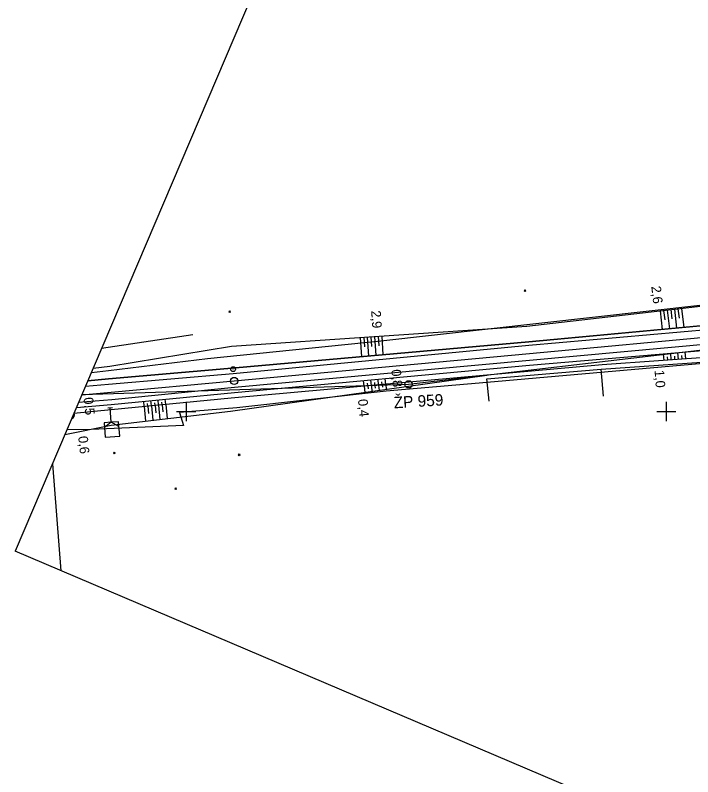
# Model space of a CAD drawing. Extents: x -805636 to -804553, y -1165340 to -1164656.
# Drawn here: x -805635.6 to -805494.5, y -1164976.1 to -1164817.4 of the extents above; entities that cross this region are included whole.
import ezdxf

# ---------------------------------------------------------------- set-up
doc = ezdxf.new("R2010")
doc.units = 0
for name, color, linetype in [('0381KM061-064P - Vrstva 1', 7, 'Continuous'), ('0381KM061-064P - Vrstva 17', 7, 'Continuous'), ('0381KM061-064P - Vrstva 4', 7, 'Continuous'), ('0381KM061-064P - Vrstva 48', 7, 'Continuous'), ('0381KM061-064P - Vrstva 49', 7, 'Continuous'), ('0381KM061-064P - Vrstva 7', 7, 'Continuous'), ('0381KM061-064P - Vrstva 8', 7, 'Continuous'), ('formát', 7, 'Continuous'), ('hran DP - hran DP', 7, 'Continuous'), ('krizky_1000 - Vrstva 1', 7, 'Continuous'), ('vyt_sit - polygon', 7, 'Continuous'), ('vyt_sit - stávající', 7, 'Continuous')]:
    doc.layers.add(name, color=color, linetype=linetype)

msp = doc.modelspace()

# ---------------------------------------------------------------- linework, layer by layer
at = {"layer": '0381KM061-064P - Vrstva 1'}
msp.add_lwpolyline([(-805621.7, -1164896.48), (-805615.58, -1164895.98), (-805590.01, -1164893.62), (-805528.48, -1164887.9), (-805486.76, -1164883.98), (-805461.3, -1164882.03), (-805437.69, -1164881.51), (-805413.27, -1164883.66)], dxfattribs=at)
at = {"layer": '0381KM061-064P - Vrstva 17'}
for p, q in [((-805598.57, -1164884.01), (-805617.61, -1164886.87)), ((-805513.07, -1164896.77), (-805513.54, -1164891.19))]:
    msp.add_line(p, q, dxfattribs=at)
msp.add_lwpolyline([(-805536.86, -1164897.86), (-805537.37, -1164893.17), (-805513.54, -1164891.19), (-805489.69, -1164889.49), (-805460.65, -1164887.61), (-805460.29, -1164888.19), (-805437.32, -1164886.99), (-805436.25, -1164891.59)], dxfattribs=at)
at = {"layer": '0381KM061-064P - Vrstva 4'}
for p, q in [((-805528.63, -1164885.47), (-805490.63, -1164881.9)), ((-805490.28, -1164882.82), (-805528.62, -1164886.23)), ((-805589.69, -1164890.91), (-805528.63, -1164885.47)), ((-805528.62, -1164886.23), (-805590.21, -1164892.16)), ((-805616.18, -1164893.18), (-805589.69, -1164890.91)), ((-805620.48, -1164893.61), (-805616.18, -1164893.18)), ((-805590.21, -1164892.16), (-805616.16, -1164894.34)), ((-805616.16, -1164894.34), (-805620.98, -1164894.78))]:
    msp.add_line(p, q, dxfattribs=at)
for points in [[(-805622.83, -1164899.13), (-805615.58, -1164898.49), (-805589.92, -1164896.02), (-805528.49, -1164890.34), (-805490.03, -1164887.06), (-805461.18, -1164884.75), (-805437.91, -1164883.87), (-805413.61, -1164886.43), (-805397.33, -1164889.69), (-805391.36, -1164890.97), (-805383.82, -1164892.41)], [(-805383.82, -1164892.41), (-805391.14, -1164890.05), (-805413.4, -1164885.24), (-805437.69, -1164883.08), (-805461.24, -1164883.62), (-805489.81, -1164885.79), (-805528.46, -1164889.37), (-805589.94, -1164895), (-805615.48, -1164897.55), (-805622.38, -1164898.08)]]:
    msp.add_lwpolyline(points, dxfattribs=at)
at = {"layer": '0381KM061-064P - Vrstva 48'}
for p, q in [((-805501.3, -1164879), (-805500.85, -1164882.86)), ((-805500.56, -1164878.91), (-805500.33, -1164880.85)), ((-805499.81, -1164878.83), (-805499.36, -1164882.72)), ((-805499.07, -1164878.74), (-805498.84, -1164880.7)), ((-805498.32, -1164878.66), (-805497.87, -1164882.58)), ((-805497.58, -1164878.57), (-805497.35, -1164880.54)), ((-805496.83, -1164878.48), (-805496.37, -1164882.44)), ((-805563.76, -1164884.57), (-805563.49, -1164888.58)), ((-805563.01, -1164884.52), (-805562.88, -1164886.51)), ((-805562.27, -1164884.47), (-805562, -1164888.44)), ((-805561.52, -1164884.42), (-805561.38, -1164886.4)), ((-805560.77, -1164884.36), (-805560.5, -1164888.31)), ((-805560.02, -1164884.31), (-805559.89, -1164886.28)), ((-805559.27, -1164884.26), (-805559.01, -1164888.18)), ((-805500.46, -1164889.32), (-805500.56, -1164887.96)), ((-805499.71, -1164889.27), (-805499.76, -1164888.58)), ((-805498.96, -1164889.21), (-805499.06, -1164887.83)), ((-805498.21, -1164889.16), (-805498.26, -1164888.46)), ((-805497.46, -1164889.11), (-805497.57, -1164887.7)), ((-805496.72, -1164889.05), (-805496.77, -1164888.34)), ((-805495.97, -1164889), (-805496.07, -1164887.57)), ((-805562.92, -1164894.73), (-805563.03, -1164893.53)), ((-805561.43, -1164894.6), (-805561.53, -1164893.4)), ((-805559.93, -1164894.46), (-805560.04, -1164893.26)), ((-805558.44, -1164894.33), (-805558.55, -1164893.12)), ((-805562.92, -1164894.73), (-805562.81, -1164895.99)), ((-805562.17, -1164894.66), (-805562.23, -1164894.06)), ((-805562.17, -1164894.66), (-805562.12, -1164895.27)), ((-805561.43, -1164894.6), (-805561.32, -1164895.78)), ((-805560.68, -1164894.53), (-805560.73, -1164893.93)), ((-805560.68, -1164894.53), (-805560.63, -1164895.1)), ((-805559.93, -1164894.46), (-805559.83, -1164895.57)), ((-805559.19, -1164894.4), (-805559.24, -1164893.79)), ((-805559.19, -1164894.4), (-805559.14, -1164894.93)), ((-805558.44, -1164894.33), (-805558.35, -1164895.36)), ((-805608.72, -1164898.95), (-805608.83, -1164897.84)), ((-805607.97, -1164898.88), (-805608.03, -1164898.32)), ((-805607.23, -1164898.81), (-805607.33, -1164897.7)), ((-805606.48, -1164898.74), (-805606.53, -1164898.18)), ((-805605.73, -1164898.67), (-805605.84, -1164897.55)), ((-805604.99, -1164898.59), (-805605.04, -1164898.04)), ((-805604.24, -1164898.52), (-805604.35, -1164897.41)), ((-805608.72, -1164898.95), (-805608.43, -1164902)), ((-805607.97, -1164898.88), (-805607.83, -1164900.4)), ((-805607.23, -1164898.81), (-805606.94, -1164901.82)), ((-805606.48, -1164898.74), (-805606.34, -1164900.24)), ((-805605.73, -1164898.67), (-805605.45, -1164901.65)), ((-805604.99, -1164898.59), (-805604.84, -1164900.08)), ((-805604.24, -1164898.52), (-805603.96, -1164901.47))]:
    msp.add_line(p, q, dxfattribs=at)
at = {"layer": '0381KM061-064P - Vrstva 49'}
for p, q in [((-805529.26, -1164875), (-805529.61, -1164874.64)), ((-805529.26, -1164874.64), (-805529.61, -1164875)), ((-805590.78, -1164879.37), (-805591.13, -1164879.01)), ((-805590.78, -1164879.01), (-805591.13, -1164879.37)), ((-805614.8, -1164908.81), (-805615.15, -1164908.45)), ((-805614.8, -1164908.45), (-805615.15, -1164908.81)), ((-805588.77, -1164909.21), (-805589.13, -1164908.86)), ((-805588.77, -1164908.86), (-805589.13, -1164909.21)), ((-805602, -1164916.26), (-805602.35, -1164915.9)), ((-805602, -1164915.9), (-805602.35, -1164916.26))]:
    msp.add_line(p, q, dxfattribs=at)
for points in [[(-805619.35, -1164890.95), (-805615.91, -1164890.53), (-805590.56, -1164886.39), (-805529.03, -1164882.21), (-805489.9, -1164877.68), (-805461.98, -1164874.39), (-805438.96, -1164873.66), (-805412.14, -1164878.2), (-805389.29, -1164884.48), (-805375.6, -1164889.14)], [(-805379.56, -1164889.14), (-805389.79, -1164885.89), (-805412.78, -1164881.05), (-805437.82, -1164878.81), (-805461.56, -1164879.34), (-805490.63, -1164881.9), (-805528.63, -1164885.47), (-805589.69, -1164890.91), (-805616.18, -1164893.18), (-805620.48, -1164893.61)], [(-805622.83, -1164899.13), (-805615.58, -1164898.49), (-805589.92, -1164896.02), (-805528.49, -1164890.34), (-805490.03, -1164887.06), (-805461.18, -1164884.75), (-805437.91, -1164883.87), (-805413.61, -1164886.43), (-805397.33, -1164889.69), (-805394.79, -1164892.28)], [(-805394.79, -1164892.28), (-805397.93, -1164890.9), (-805413.8, -1164887.77), (-805437.96, -1164885.62), (-805460.38, -1164886.37), (-805489.93, -1164888.57), (-805513.35, -1164890.24), (-805537.4, -1164892.44), (-805590.64, -1164897.22), (-805615.62, -1164899.61), (-805623.38, -1164900.43)], [(-805625.24, -1164904.79), (-805615.6, -1164902.86), (-805590.78, -1164899.89), (-805537.4, -1164892.44)]]:
    msp.add_lwpolyline(points, dxfattribs=at)
at = {"layer": '0381KM061-064P - Vrstva 7'}
for p, q in [((-805590.27, -1164891.15), (-805590.17, -1164891.14)), ((-805615.33, -1164899.2), (-805616.33, -1164899.28)), ((-805615.58, -1164902.23), (-805615.83, -1164899.24))]:
    msp.add_line(p, q, dxfattribs=at)
for points in [[(-805615.58, -1164902.23), (-805617.08, -1164902.35), (-805616.83, -1164905.34), (-805613.84, -1164905.1), (-805614.09, -1164902.11), (-805615.58, -1164902.23)], [(-805614, -1164903.1), (-805615.58, -1164902.23), (-805616.99, -1164903.35)]]:
    msp.add_lwpolyline(points, dxfattribs=at)
for centre, radius in [((-805590.22, -1164891.15), 0.5), ((-805590, -1164893.62), 0.75)]:
    msp.add_circle(centre, radius, dxfattribs=at)
at = {"layer": '0381KM061-064P - Vrstva 8'}
for p, q in [((-805623.32, -1164900.29), (-805623.86, -1164901.55)), ((-805627.84, -1164910.91), (-805626.08, -1164933.16))]:
    msp.add_line(p, q, dxfattribs=at)
msp.add_arc((-805624.26, -1164900.63), 1, 293.9534, 19.9498, dxfattribs=at)
at = {"layer": 'formát'}
for p in [(-805519.31, -1164655.82), (-805055.88, -1165175.77)]:
    msp.add_line(p, (-805635.59, -1164929.12), dxfattribs=at)
at = {"layer": 'hran DP - hran DP'}
for p, q in [((-805559.43, -1164885.25), (-805493.02, -1164877.83)), ((-805595.52, -1164888.96), (-805559.43, -1164885.25)), ((-805472.98, -1164888.24), (-805537.37, -1164893.92)), ((-805616.15, -1164891.42), (-805595.52, -1164888.96)), ((-805619.74, -1164891.88), (-805616.15, -1164891.42)), ((-805537.37, -1164893.92), (-805558.32, -1164895.77)), ((-805558.32, -1164895.77), (-805589.42, -1164899.19)), ((-805589.42, -1164899.19), (-805601.38, -1164900.18)), ((-805601.38, -1164900.18), (-805600.58, -1164902.92)), ((-805600.58, -1164902.92), (-805621.39, -1164903.78)), ((-805621.39, -1164903.78), (-805624.8, -1164903.76))]:
    msp.add_line(p, q, dxfattribs=at)
at = {"layer": 'krizky_1000 - Vrstva 1'}
for points in [[(-805600, -1164898), (-805600, -1164902)], [(-805500, -1164898), (-805500, -1164902)], [(-805602, -1164900), (-805598, -1164900)], [(-805502, -1164900), (-805498, -1164900)]]:
    msp.add_lwpolyline(points, dxfattribs=at)
at = {"layer": 'vyt_sit - polygon'}
for p, q in [((-805412.1, -1164877.75), (-805553.67, -1164894.32)), ((-805553.67, -1164894.32), (-805621.71, -1164896.51))]:
    msp.add_line(p, q, dxfattribs=at)
at = {"layer": 'vyt_sit - stávající'}
msp.add_line((-805553.71, -1164894.29), (-805553.63, -1164894.35), dxfattribs=at)
msp.add_circle((-805553.67, -1164894.32), 0.756, dxfattribs=at)

# ---------------------------------------------------------------- texts
at = {"layer": '0381KM061-064P - Vrstva 48'}
for s, rotation, p in [('2,6', 276.6062, (-805503.14, -1164873.92)), ('2,9', 273.8809, (-805561.47, -1164878.99)), ('0,8', 275.1319, (-805557.27, -1164891.28)), ('1,0', 274.074, (-805502.45, -1164891.38)), ('0,5', 276.0149, (-805621.37, -1164897.12)), ('0,4', 275.1319, (-805564.22, -1164897.47)), ('0,6', 276.0149, (-805622.49, -1164905.2))]:
    msp.add_text(s, height=2, rotation=rotation, dxfattribs=at).set_placement(p)
at = {"layer": 'vyt_sit - stávající'}
msp.add_text('ŽP 959', height=2.4, rotation=3.5611, dxfattribs=at).set_placement((-805556.7, -1164899.34))

doc.saveas('drawing.dxf')
